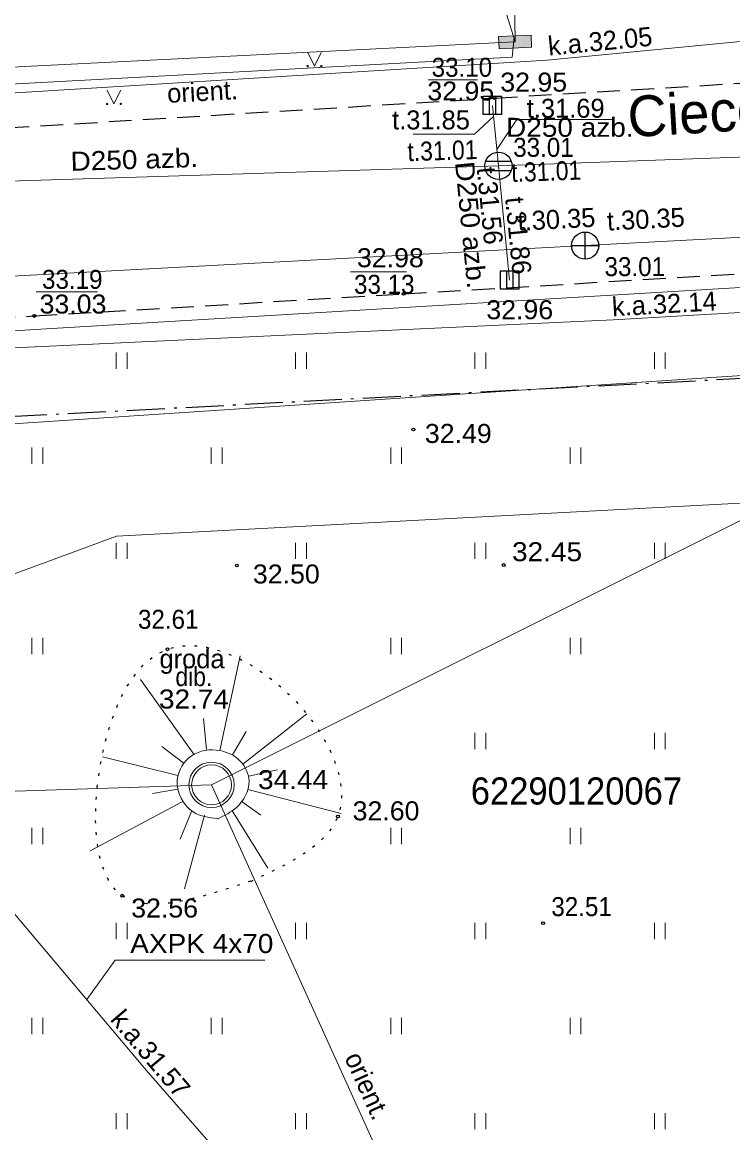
# Model space of a CAD drawing. Extents: x 380758 to 381729, y 283236 to 283533.
# Drawn here: x 381402.45 to 381428.59, y 283322.44 to 283363.33 of the extents above; entities that cross this region are included whole.
import ezdxf
from ezdxf.enums import TextEntityAlignment as Align

# ---------------------------------------------------------------- set-up
doc = ezdxf.new("R2010")
doc.units = 0
doc.header["$LTSCALE"] = 0.28
for name, pattern in [('DOT_DASHED', [7.7, 5, -1.2, 0.3, -1.2]), ('DOTTED', [1.5, 0.3, -1.2]), ('MEDIUM_DASHED', [4.5, 3, -1.5])]:
    doc.linetypes.add(name, pattern=pattern)
for name, color, linetype, lineweight in [('1', 7, 'Continuous', 13), ('11', 7, 'Continuous', 13), ('12', 7, 'Continuous', 13), ('17', 7, 'Continuous', 13), ('18', 7, 'Continuous', 13), ('23', 7, 'Continuous', 13), ('29', 7, 'DOT_DASHED', 25), ('31', 7, 'Continuous', 13), ('35', 7, 'Continuous', 13), ('37', 7, 'MEDIUM_DASHED', 13), ('38', 7, 'Continuous', 25), ('45', 7, 'Continuous', 13), ('47', 7, 'Continuous', 13), ('48', 7, 'Continuous', 25), ('51', 7, 'Continuous', 25), ('58', 7, 'Continuous', 25), ('7', 7, 'Continuous', 13), ('9', 7, 'Continuous', 13)]:
    doc.layers.add(name, color=color, linetype=linetype, lineweight=lineweight)
doc.layers.add('56', color=7, linetype='Continuous')
doc.layers.add('59', color=7, linetype='Continuous')

msp = doc.modelspace()

# ---------------------------------------------------------------- hatches: boundary and pattern name
at = {"layer": '18'}
msp.add_hatch(color=256, dxfattribs=at).paths.add_polyline_path([(381419.972, 283362.801), (381421.171, 283362.858), (381421.192, 283362.409), (381419.993, 283362.352)])

# ---------------------------------------------------------------- linework, layer by layer
at = {"layer": '1'}
msp.add_line((381395.278, 283348.094), (381431.118, 283350.472), dxfattribs=at)
at = {"layer": '11'}
for p, q in [((381419.973, 283358.043), (381440.373, 283358.767)), ((381395.567, 283357.283), (381419.973, 283358.043))]:
    msp.add_line(p, q, dxfattribs=at)
for points in [[(381419.748, 283360.268), (381419.973, 283358.043), (381420.385, 283353.836)], [(381416.831, 283359.207), (381419.091, 283359.207), (381419.789, 283359.859)], [(381424.233, 283359.753), (381420.649, 283359.753), (381419.912, 283358.646)]]:
    msp.add_lwpolyline(points, dxfattribs=at)
at = {"layer": '12'}
for radius in [0.8334, 0.7333]:
    msp.add_circle((381409.4176, 283335.2497), radius, dxfattribs=at)
at = {"layer": '17'}
msp.add_lwpolyline([(381389.117, 283351.081), (381395.098, 283351.508), (381402.928, 283352.014), (381416.512, 283352.829), (381433.409, 283353.834), (381450.312, 283354.874), (381458.856, 283355.374)], dxfattribs=at)
at = {"layer": '18'}
msp.add_lwpolyline([(381419.972, 283362.801), (381421.171, 283362.858), (381421.192, 283362.409), (381419.993, 283362.352)], close=True, dxfattribs=at)
at = {"layer": '23'}
for p, q in [((381405.909, 283350.566), (381405.909, 283351.166)), ((381406.309, 283350.566), (381406.309, 283351.166)), ((381412.509, 283350.566), (381412.509, 283351.166)), ((381412.909, 283350.566), (381412.909, 283351.166)), ((381419.109, 283350.566), (381419.109, 283351.166)), ((381419.509, 283350.566), (381419.509, 283351.166)), ((381425.709, 283350.566), (381425.709, 283351.166)), ((381426.109, 283350.566), (381426.109, 283351.166)), ((381402.809, 283347.066), (381402.809, 283347.666)), ((381403.209, 283347.066), (381403.209, 283347.666)), ((381409.409, 283347.066), (381409.409, 283347.666)), ((381409.809, 283347.066), (381409.809, 283347.666)), ((381416.009, 283347.066), (381416.009, 283347.666)), ((381416.409, 283347.066), (381416.409, 283347.666)), ((381422.609, 283347.066), (381422.609, 283347.666)), ((381423.009, 283347.066), (381423.009, 283347.666)), ((381405.909, 283343.566), (381405.909, 283344.166)), ((381406.309, 283343.566), (381406.309, 283344.166)), ((381412.509, 283343.566), (381412.509, 283344.166)), ((381412.909, 283343.566), (381412.909, 283344.166)), ((381419.109, 283343.566), (381419.109, 283344.166)), ((381419.509, 283343.566), (381419.509, 283344.166)), ((381425.709, 283343.566), (381425.709, 283344.166)), ((381426.109, 283343.566), (381426.109, 283344.166)), ((381402.809, 283340.066), (381402.809, 283340.666)), ((381403.209, 283340.066), (381403.209, 283340.666)), ((381416.009, 283340.066), (381416.009, 283340.666)), ((381416.409, 283340.066), (381416.409, 283340.666)), ((381422.609, 283340.066), (381422.609, 283340.666)), ((381423.009, 283340.066), (381423.009, 283340.666)), ((381419.109, 283336.566), (381419.109, 283337.166)), ((381419.509, 283336.566), (381419.509, 283337.166)), ((381425.709, 283336.566), (381425.709, 283337.166)), ((381426.109, 283336.566), (381426.109, 283337.166)), ((381402.809, 283333.066), (381402.809, 283333.666)), ((381403.209, 283333.066), (381403.209, 283333.666)), ((381416.009, 283333.066), (381416.009, 283333.666)), ((381416.409, 283333.066), (381416.409, 283333.666)), ((381422.609, 283333.066), (381422.609, 283333.666)), ((381423.009, 283333.066), (381423.009, 283333.666)), ((381405.909, 283329.566), (381405.909, 283330.166)), ((381406.309, 283329.566), (381406.309, 283330.166)), ((381412.509, 283329.566), (381412.509, 283330.166)), ((381412.909, 283329.566), (381412.909, 283330.166)), ((381419.109, 283329.566), (381419.109, 283330.166)), ((381419.509, 283329.566), (381419.509, 283330.166)), ((381425.709, 283329.566), (381425.709, 283330.166)), ((381426.109, 283329.566), (381426.109, 283330.166)), ((381402.809, 283326.066), (381402.809, 283326.666)), ((381403.209, 283326.066), (381403.209, 283326.666)), ((381409.409, 283326.066), (381409.409, 283326.666)), ((381409.809, 283326.066), (381409.809, 283326.666)), ((381416.009, 283326.066), (381416.009, 283326.666)), ((381416.409, 283326.066), (381416.409, 283326.666)), ((381422.609, 283326.066), (381422.609, 283326.666)), ((381423.009, 283326.066), (381423.009, 283326.666)), ((381405.909, 283322.566), (381405.909, 283323.166)), ((381406.309, 283322.566), (381406.309, 283323.166)), ((381412.509, 283322.566), (381412.509, 283323.166)), ((381412.909, 283322.566), (381412.909, 283323.166)), ((381419.109, 283322.566), (381419.109, 283323.166)), ((381419.509, 283322.566), (381419.509, 283323.166)), ((381425.709, 283322.566), (381425.709, 283323.166)), ((381426.109, 283322.566), (381426.109, 283323.166))]:
    msp.add_line(p, q, dxfattribs=at)
for points in [[(381412.956, 283362.21), (381413.206, 283361.71), (381413.456, 283362.21)], [(381405.579, 283360.822), (381405.829, 283360.322), (381406.079, 283360.822)]]:
    msp.add_lwpolyline(points, dxfattribs=at)
for centre, radius in [((381412.9557, 283361.7095), 0.028), ((381413.4557, 283361.7095), 0.0263), ((381405.5787, 283360.3219), 0.028), ((381406.0787, 283360.3219), 0.0263)]:
    msp.add_circle(centre, radius, dxfattribs=at)
at = {"layer": '29'}
msp.add_lwpolyline([(381380.81, 283334.546), (381395.244, 283334.434), (381395.42, 283344.863), (381381.932, 283344.092), (381382.445, 283347.789), (381431.659, 283350.36)], dxfattribs=at)
at = {"layer": '31'}
for p, q in [((381409.723, 283336.512), (381410.476, 283339.999)), ((381408.763, 283336.383), (381406.806, 283339.133)), ((381410.564, 283336.017), (381412.918, 283337.869)), ((381409.227, 283336.553), (381409.116, 283337.698)), ((381410.193, 283336.349), (381410.688, 283337.216)), ((381408.408, 283336.032), (381407.591, 283336.664)), ((381408.183, 283335.59), (381405.406, 283336.279)), ((381410.785, 283335.574), (381411.845, 283335.798)), ((381408.181, 283335.093), (381407.241, 283334.931)), ((381410.753, 283335.08), (381414.181, 283334.194)), ((381408.337, 283334.62), (381404.95, 283332.821)), ((381410.549, 283334.626), (381411.227, 283334.137)), ((381408.682, 283334.272), (381408.265, 283333.255)), ((381409.163, 283334.137), (381408.423, 283331.427)), ((381410.165, 283334.314), (381411.484, 283332.183))]:
    msp.add_line(p, q, dxfattribs=at)
at = {"layer": '31', "linetype": 'DOTTED', "lineweight": 25}
msp.add_spline([(381410.866, 283331.706), (381406.133, 283331.166), (381405.371, 283336.204), (381407.796, 283340.241), (381412.539, 283338.303), (381414.066, 283334.085), (381410.791, 283331.656)], degree=3, dxfattribs=at)
at = {"layer": '31'}
msp.add_spline([(381409.645, 283334.005), (381408.737, 283334.253), (381408.159, 283335.437), (381408.682, 283336.319), (381409.728, 283336.511), (381410.471, 283336.126), (381410.801, 283335.382), (381410.333, 283334.418), (381409.663, 283334.004)], degree=3, dxfattribs=at)
at = {"layer": '35'}
msp.add_lwpolyline([(381401.803, 283342.89), (381405.92, 283344.402), (381432.116, 283345.788), (381434.467, 283310.113), (381430.26, 283307.951)], dxfattribs=at)
at = {"layer": '37', "lineweight": 25}
for points in [[(381309.426, 283365.712), (381316.201, 283360.727), (381318.377, 283359.189), (381320.24, 283357.84), (381330.826, 283355.148), (381345.75, 283356.042), (381361.347, 283356.997), (381379.416, 283358.112), (381395.576, 283359.052), (381419.83, 283360.537), (381435.717, 283361.494), (381453.632, 283362.598)], [(381389.081, 283351.58), (381395.064, 283352.007), (381402.897, 283352.513), (381416.482, 283353.328), (381433.379, 283354.333), (381450.282, 283355.373), (381458.878, 283355.876)]]:
    msp.add_lwpolyline(points, dxfattribs=at)
at = {"layer": '38'}
for p, q in [((381423.16, 283354.603), (381423.16, 283355.603)), ((381422.66, 283355.103), (381423.66, 283355.103))]:
    msp.add_line(p, q, dxfattribs=at)
msp.add_circle((381423.16, 283355.103), 0.5, dxfattribs=at)
at = {"layer": '45'}
msp.add_lwpolyline([(381392.214, 283360.116), (381421.765, 283361.936), (381446.512, 283364.342), (381453.262, 283365.948)], dxfattribs=at)
at = {"layer": '47'}
msp.add_lwpolyline([(381327.333, 283349.98), (381423.16, 283355.103), (381470.505, 283357.6)], dxfattribs=at)
at = {"layer": '48'}
for p, q in [((381419.635, 283360.606), (381419.635, 283359.931)), ((381419.86, 283360.606), (381419.86, 283359.931)), ((381419.505, 283358.218), (381420.441, 283358.218)), ((381419.505, 283357.868), (381420.441, 283357.868)), ((381420.272, 283354.174), (381420.272, 283353.499)), ((381420.497, 283354.174), (381420.497, 283353.499))]:
    msp.add_line(p, q, dxfattribs=at)
for points in [[(381419.41, 283360.606), (381420.085, 283360.606), (381420.085, 283359.931), (381419.41, 283359.931)], [(381420.047, 283354.174), (381420.722, 283354.174), (381420.722, 283353.499), (381420.047, 283353.499)]]:
    msp.add_lwpolyline(points, close=True, dxfattribs=at)
msp.add_circle((381419.973, 283358.043), 0.5, dxfattribs=at)
at = {"layer": '58', "lineweight": 13}
for p, q in [((381417.393, 283361.21), (381419.205, 283361.21)), ((381414.533, 283354.136), (381416.589, 283354.136)), ((381402.968, 283353.401), (381405.22, 283353.401))]:
    msp.add_line(p, q, dxfattribs=at)
at = {"layer": '58'}
for centre in [(381419.83, 283360.5371), (381416.482, 283353.3281), (381402.897, 283352.5131), (381416.842, 283348.3341), (381410.35, 283343.3251), (381420.167, 283343.3431), (381407.796, 283340.2411), (381414.066, 283334.0851), (381406.133, 283331.1661), (381421.613, 283330.1571)]:
    msp.add_circle(centre, 0.0534, dxfattribs=at)
at = {"layer": '7'}
for p, q in [((381420.582, 283362.605), (381413.888, 283384.429)), ((381420.582, 283362.605), (381420.332, 283380.046)), ((381395.348, 283361.344), (381420.582, 283362.605)), ((381404.832, 283327.343), (381405.868, 283328.8)), ((381405.868, 283328.8), (381411.381, 283328.797))]:
    msp.add_line(p, q, dxfattribs=at)
for points in [[(381392.676, 283360.539), (381416.363, 283361.822), (381420.478, 283362.045), (381420.557, 283362.77)], [(381460.834, 283354.062), (381441.392, 283353.365), (381424.187, 283352.367), (381396.884, 283351.089)], [(381416.639, 283313.73), (381407.089, 283324.656), (381399.011, 283334.242)]]:
    msp.add_lwpolyline(points, dxfattribs=at)
at = {"layer": '9'}
for p, q in [((381505.481, 283383.309), (381409.418, 283335.25)), ((381409.418, 283335.25), (381417.299, 283317.844))]:
    msp.add_line(p, q, dxfattribs=at)
msp.add_lwpolyline([(381159.963, 283331.675), (381191.524, 283331.747), (381195.757, 283331.812), (381227.539, 283340.262), (381286.928, 283343.391), (381326.31, 283339.103), (381385.472, 283334.479), (381409.418, 283335.25)], dxfattribs=at)

# ---------------------------------------------------------------- texts
at = {"layer": '11'}
for s, p in [('t.31.69', (381422.446, 283359.811)), ('t.31.85', (381417.492, 283359.382))]:
    msp.add_text(s, height=0.7, dxfattribs=at).set_placement(p, align=Align.CENTER)
at = {"layer": '11', "width": 1.1}
msp.add_text('D250 azb.', height=0.7, dxfattribs=at).set_placement((381422.5985, 283359.109), align=Align.CENTER)
at = {"layer": '11'}
for s, rotation, width, p in [('D250 azb.', 1.784, 1.1, (381406.5881, 283357.9267)), ('t.31.01', 1.784, 0.9, (381417.9226, 283358.2524)), ('D250 azb.', 275.593, 1.1, (381418.6022, 283355.8316)), ('t.31.01', 2.033, 0.9, (381421.7421, 283357.4901))]:
    msp.add_text(s, height=0.7, rotation=rotation, dxfattribs=dict(at, width=width)).set_placement(p, align=Align.CENTER)
for s, p in [('t.31.56', (381419.3126, 283356.5396)), ('t.31.86', (381420.3576, 283355.4386))]:
    msp.add_text(s, height=0.7, rotation=275.593, dxfattribs=at).set_placement(p, align=Align.CENTER)
at = {"layer": '12', "width": 1.1}
msp.add_text('34.44', height=0.7, dxfattribs=at).set_placement((381411.127, 283335.092))
at = {"layer": '38', "width": 0.95}
msp.add_text('33.01', height=0.7, dxfattribs=at).set_placement((381423.876, 283353.98))
at = {"layer": '45'}
msp.add_text('k.a.32.05', height=0.7, rotation=5.553, dxfattribs=at).set_placement((381421.829, 283362.096))
at = {"layer": '47'}
for rotation, p in [(3.06, (381422.1253, 283355.725)), (3.019, (381425.4131, 283355.7309))]:
    msp.add_text('t.30.35', height=0.7, rotation=rotation, dxfattribs=at).set_placement(p, align=Align.CENTER)
at = {"layer": '48'}
for s, width, p in [('32.95', 1.05, (381420.04, 283360.774)), ('33.01', 0.95, (381420.516, 283358.372)), ('32.96', 1.05, (381419.527, 283352.393))]:
    msp.add_text(s, height=0.7, dxfattribs=dict(at, width=width)).set_placement(p)
at = {"layer": '51'}
msp.add_text('groda', height=0.7, dxfattribs=at).set_placement((381408.6995, 283339.542), align=Align.CENTER)
for s, width, p in [('dib.', 0.9, (381408.767, 283338.884)), ('32.74', 1.1, (381408.771, 283338.06))]:
    msp.add_text(s, height=0.7, dxfattribs=dict(at, width=width)).set_placement(p, align=Align.CENTER)
at = {"layer": '56'}
msp.add_text('Cieceres iela', height=1.5, rotation=3.433, dxfattribs=at).set_placement((381424.769, 283359.092))
at = {"layer": '58'}
for s, width, p in [('33.10', 0.95, (381417.515, 283361.319)), ('32.95', 1.05, (381417.357, 283360.447)), ('32.98', 1.05, (381414.767, 283354.307)), ('33.19', 0.95, (381403.182, 283353.512)), ('33.13', 0.95, (381414.66, 283353.328)), ('33.03', 1.05, (381403.091, 283352.602)), ('32.49', 1.05, (381417.266, 283347.838)), ('32.45', 1.1, (381420.473, 283343.484)), ('32.50', 1.05, (381410.939, 283342.664)), ('32.61', 0.95, (381406.711, 283340.995)), ('32.60', 1.05, (381414.608, 283333.943)), ('32.56', 1.05, (381406.462, 283330.364)), ('32.51', 0.95, (381421.919, 283330.416))]:
    msp.add_text(s, height=0.7, dxfattribs=dict(at, width=width)).set_placement(p)
at = {"layer": '59', "width": 0.95}
msp.add_text('62290120067', height=1, dxfattribs=at).set_placement((381418.955, 283334.524))
at = {"layer": '7'}
msp.add_text('orient.', height=0.7, rotation=3.1, dxfattribs=at).set_placement((381409.1016, 283360.4272), align=Align.CENTER)
for s, rotation, p in [('k.a.32.14', 3.32, (381424.169, 283352.498)), ('k.a.31.57', 310.421, (381405.661, 283326.593))]:
    msp.add_text(s, height=0.7, rotation=rotation, dxfattribs=at).set_placement(p)
at = {"layer": '7', "width": 1.1}
msp.add_text('AXPK 4x70', height=0.7, dxfattribs=at).set_placement((381406.426, 283329.058))
at = {"layer": '9'}
msp.add_text('orient.', height=0.7, rotation=294.361, dxfattribs=at).set_placement((381414.8306, 283324.0249), align=Align.CENTER)

doc.saveas('drawing.dxf')
